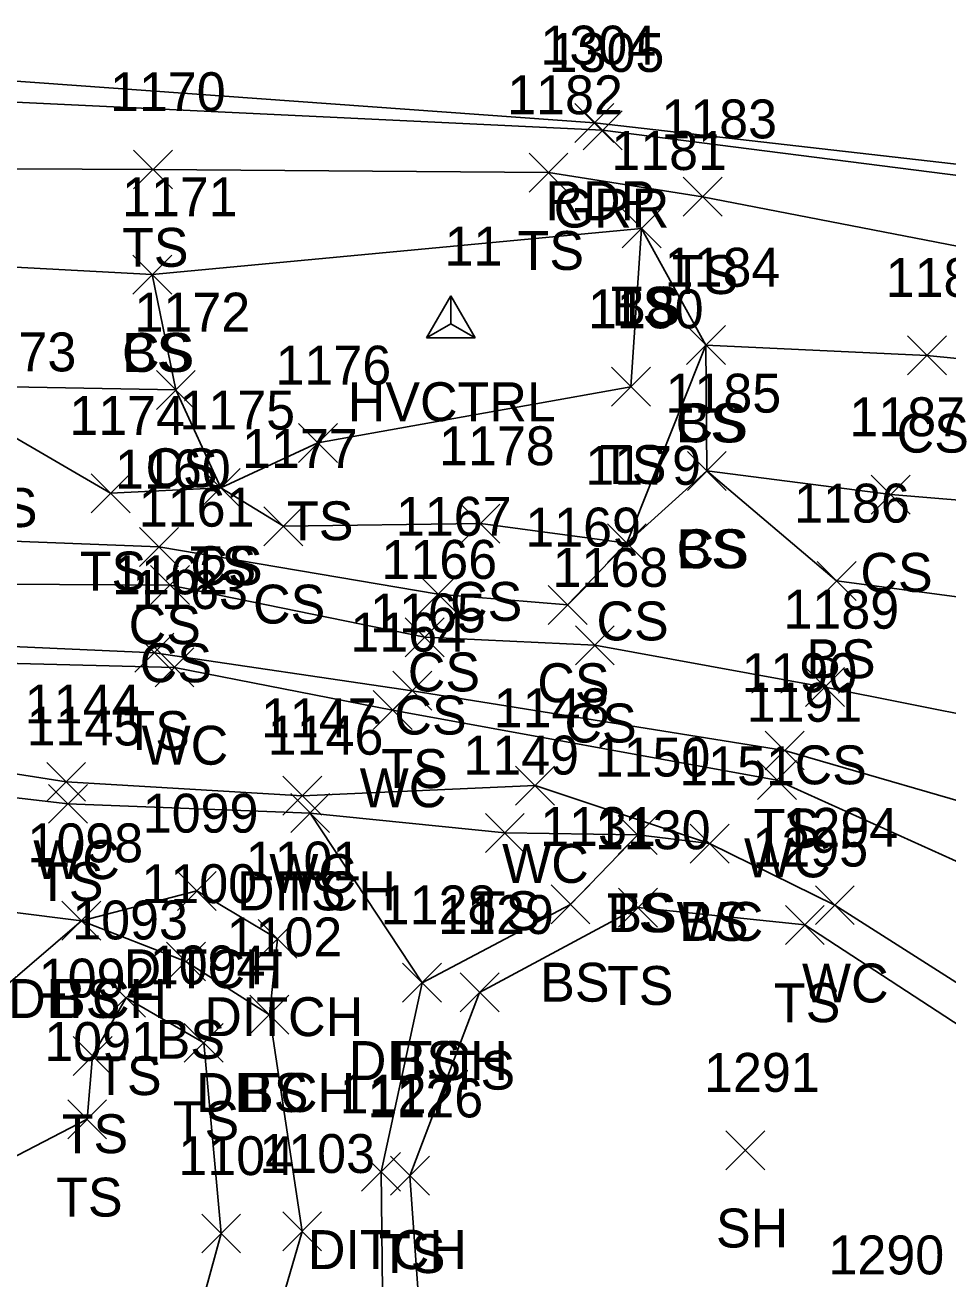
# Model space of a CAD drawing. Extents: x 1514253 to 1516033, y 782541 to 785002.
# Drawn here: x 1515320.5 to 1515367.9, y 782620.4 to 782684.8 of the extents above; entities that cross this region are included whole.
import ezdxf

# ---------------------------------------------------------------- set-up
doc = ezdxf.new("R2010")
doc.units = 0
for name, color, linetype in [('C_A', 7, 'Continuous'), ('C_I', 7, 'Continuous'), ('CPSM', 7, 'Continuous'), ('D_A', 7, 'Continuous'), ('D_I', 7, 'Continuous'), ('D_TIC', 7, 'Continuous'), ('DD', 7, 'Continuous'), ('L_A', 7, 'Continuous'), ('L_I', 7, 'Continuous'), ('L_TIC', 7, 'Continuous'), ('LAWE', 7, 'Continuous'), ('LELB', 7, 'Continuous'), ('P_A', 7, 'Continuous'), ('P_I', 7, 'Continuous'), ('P_TIC', 7, 'Continuous'), ('PET', 7, 'Continuous'), ('R_A', 7, 'Continuous'), ('R_I', 7, 'Continuous'), ('R_TIC', 7, 'Continuous'), ('RGR', 7, 'Continuous')]:
    doc.layers.add(name, color=color, linetype=linetype)

msp = doc.modelspace()

# ---------------------------------------------------------------- linework, layer by layer
at = {"layer": 'CPSM'}
for p, q in [((1515341.122, 782668.734), (1515342.372, 782670.899)), ((1515343.622, 782668.734), (1515342.372, 782670.899)), ((1515342.372, 782669.456), (1515342.372, 782670.899)), ((1515341.122, 782668.734), (1515342.372, 782669.456)), ((1515342.372, 782669.456), (1515342.372, 782669.456)), ((1515342.372, 782669.456), (1515343.622, 782668.734)), ((1515341.122, 782668.734), (1515343.622, 782668.734))]:
    msp.add_line(p, q, dxfattribs=at)
at = {"layer": 'D_TIC'}
for points in [[(1515334.13, 782643.312), (1515336.13, 782645.312)], [(1515336.13, 782643.312), (1515334.13, 782645.312)], [(1515328.306, 782639.309), (1515330.306, 782641.309)], [(1515330.306, 782639.309), (1515328.306, 782641.309)], [(1515322.367, 782637.781), (1515324.367, 782639.781)], [(1515324.367, 782637.781), (1515322.367, 782639.781)], [(1515332.451, 782636.848), (1515334.451, 782638.848)], [(1515334.451, 782636.848), (1515332.451, 782638.848)], [(1515339.884, 782634.592), (1515341.884, 782636.592)], [(1515341.884, 782634.592), (1515339.884, 782636.592)], [(1515332.036, 782632.949), (1515334.036, 782634.949)], [(1515334.036, 782632.949), (1515332.036, 782634.949)], [(1515337.78, 782624.875), (1515339.78, 782626.875)], [(1515339.78, 782624.875), (1515337.78, 782626.875)], [(1515333.721, 782621.814), (1515335.721, 782623.814)], [(1515335.721, 782621.814), (1515333.721, 782623.814)]]:
    msp.add_lwpolyline(points, dxfattribs=at)
at = {"layer": 'DD'}
for points in [[(1515199.394, 782648.84), (1515235.483, 782648.45), (1515272.163, 782648.844), (1515285.608, 782648.488), (1515294.464, 782648.384), (1515312.17, 782640.182), (1515323.367, 782638.781), (1515329.306, 782640.309), (1515333.451, 782637.848), (1515333.036, 782633.949), (1515334.721, 782622.814), (1515328.394, 782601.12)], [(1515357.883, 782606.277), (1515350.175, 782606.05), (1515345.522, 782607.313), (1515338.903, 782615.134), (1515338.78, 782625.875), (1515340.884, 782635.592), (1515335.13, 782644.312)]]:
    msp.add_lwpolyline(points, dxfattribs=at)
at = {"layer": 'L_TIC'}
for points in [[(1515326.05, 782676.392), (1515328.05, 782678.392)], [(1515328.05, 782676.392), (1515326.05, 782678.392)], [(1515346.388, 782676.23), (1515348.388, 782678.23)], [(1515348.388, 782676.23), (1515346.388, 782678.23)], [(1515354.314, 782674.991), (1515356.314, 782676.991)], [(1515356.314, 782674.991), (1515354.314, 782676.991)], [(1515351.175, 782673.367), (1515353.175, 782675.367)], [(1515353.175, 782673.367), (1515351.175, 782675.367)], [(1515351.175, 782673.367), (1515353.175, 782675.367)], [(1515353.175, 782673.367), (1515351.175, 782675.367)], [(1515326.016, 782670.989), (1515328.016, 782672.989)], [(1515328.016, 782670.989), (1515326.016, 782672.989)], [(1515326.016, 782670.989), (1515328.016, 782672.989)], [(1515328.016, 782670.989), (1515326.016, 782672.989)], [(1515354.484, 782667.368), (1515356.484, 782669.368)], [(1515356.484, 782667.368), (1515354.484, 782669.368)], [(1515354.484, 782667.368), (1515356.484, 782669.368)], [(1515356.484, 782667.368), (1515354.484, 782669.368)], [(1515365.848, 782666.84), (1515367.848, 782668.84)], [(1515367.848, 782666.84), (1515365.848, 782668.84)], [(1515327.224, 782665.061), (1515329.224, 782667.061)], [(1515329.224, 782665.061), (1515327.224, 782667.061)], [(1515327.224, 782665.061), (1515329.224, 782667.061)], [(1515329.224, 782665.061), (1515327.224, 782667.061)], [(1515350.626, 782665.228), (1515352.626, 782667.228)], [(1515352.626, 782665.228), (1515350.626, 782667.228)], [(1515334.531, 782662.335), (1515336.531, 782664.335)], [(1515336.531, 782662.335), (1515334.531, 782664.335)], [(1515354.529, 782660.896), (1515356.529, 782662.896)], [(1515356.529, 782660.896), (1515354.529, 782662.896)], [(1515354.529, 782660.896), (1515356.529, 782662.896)], [(1515356.529, 782660.896), (1515354.529, 782662.896)], [(1515329.533, 782660.03), (1515331.533, 782662.03)], [(1515331.533, 782660.03), (1515329.533, 782662.03)], [(1515329.533, 782660.03), (1515331.533, 782662.03)], [(1515331.533, 782660.03), (1515329.533, 782662.03)], [(1515323.873, 782659.753), (1515325.873, 782661.753)], [(1515325.873, 782659.753), (1515323.873, 782661.753)], [(1515363.984, 782659.684), (1515365.984, 782661.684)], [(1515365.984, 782659.684), (1515363.984, 782661.684)], [(1515332.755, 782658.052), (1515334.755, 782660.052)], [(1515334.755, 782658.052), (1515332.755, 782660.052)], [(1515342.884, 782658.192), (1515344.884, 782660.192)], [(1515344.884, 782658.192), (1515342.884, 782660.192)], [(1515326.358, 782656.995), (1515328.358, 782658.995)], [(1515328.358, 782656.995), (1515326.358, 782658.995)], [(1515350.413, 782657.187), (1515352.413, 782659.187)], [(1515352.413, 782657.187), (1515350.413, 782659.187)], [(1515350.413, 782657.187), (1515352.413, 782659.187)], [(1515352.413, 782657.187), (1515350.413, 782659.187)], [(1515326.927, 782655.035), (1515328.927, 782657.035)], [(1515328.927, 782655.035), (1515326.927, 782657.035)], [(1515361.199, 782655.243), (1515363.199, 782657.243)], [(1515363.199, 782655.243), (1515361.199, 782657.243)], [(1515340.712, 782654.566), (1515342.712, 782656.566)], [(1515342.712, 782654.566), (1515340.712, 782656.566)], [(1515347.371, 782654.012), (1515349.371, 782656.012)], [(1515349.371, 782654.012), (1515347.371, 782656.012)], [(1515340.024, 782652.35), (1515342.024, 782654.35)], [(1515342.024, 782652.35), (1515340.024, 782654.35)], [(1515326.12, 782651.556), (1515328.12, 782653.556)], [(1515328.12, 782651.556), (1515326.12, 782653.556)], [(1515348.767, 782651.941), (1515350.767, 782653.941)], [(1515350.767, 782651.941), (1515348.767, 782653.941)], [(1515327.158, 782650.8), (1515329.158, 782652.8)], [(1515329.158, 782650.8), (1515327.158, 782652.8)], [(1515339.38, 782649.599), (1515341.38, 782651.599)], [(1515341.38, 782649.599), (1515339.38, 782651.599)], [(1515360.602, 782649.791), (1515362.602, 782651.791)], [(1515362.602, 782649.791), (1515360.602, 782651.791)], [(1515338.372, 782648.611), (1515340.372, 782650.611)], [(1515340.372, 782648.611), (1515338.372, 782650.611)], [(1515358.526, 782646.53), (1515360.526, 782648.53)], [(1515360.526, 782646.53), (1515358.526, 782648.53)], [(1515321.585, 782644.92), (1515323.585, 782646.92)], [(1515323.585, 782644.92), (1515321.585, 782646.92)], [(1515345.696, 782644.723), (1515347.696, 782646.723)], [(1515347.696, 782644.723), (1515345.696, 782646.723)], [(1515358.133, 782645.008), (1515360.133, 782647.008)], [(1515360.133, 782645.008), (1515358.133, 782647.008)], [(1515321.678, 782643.788), (1515323.678, 782645.788)], [(1515323.678, 782643.788), (1515321.678, 782645.788)], [(1515333.724, 782644.203), (1515335.724, 782646.203)], [(1515335.724, 782644.203), (1515333.724, 782646.203)], [(1515334.13, 782643.312), (1515336.13, 782645.312)], [(1515336.13, 782643.312), (1515334.13, 782645.312)], [(1515344.143, 782642.295), (1515346.143, 782644.295)], [(1515346.143, 782642.295), (1515344.143, 782644.295)], [(1515350.972, 782642.192), (1515352.972, 782644.192)], [(1515352.972, 782642.192), (1515350.972, 782644.192)], [(1515350.972, 782642.192), (1515352.972, 782644.192)], [(1515352.972, 782642.192), (1515350.972, 782644.192)], [(1515354.669, 782641.743), (1515356.669, 782643.743)], [(1515356.669, 782641.743), (1515354.669, 782643.743)], [(1515354.669, 782641.743), (1515356.669, 782643.743)], [(1515356.669, 782641.743), (1515354.669, 782643.743)], [(1515347.518, 782638.619), (1515349.518, 782640.619)], [(1515349.518, 782638.619), (1515347.518, 782640.619)], [(1515350.986, 782638.451), (1515352.986, 782640.451)], [(1515352.986, 782638.451), (1515350.986, 782640.451)], [(1515361.112, 782638.578), (1515363.112, 782640.578)], [(1515363.112, 782638.578), (1515361.112, 782640.578)], [(1515361.112, 782638.578), (1515363.112, 782640.578)], [(1515363.112, 782638.578), (1515361.112, 782640.578)], [(1515322.367, 782637.781), (1515324.367, 782639.781)], [(1515324.367, 782637.781), (1515322.367, 782639.781)], [(1515359.567, 782637.564), (1515361.567, 782639.564)], [(1515361.567, 782637.564), (1515359.567, 782639.564)], [(1515359.567, 782637.564), (1515361.567, 782639.564)], [(1515361.567, 782637.564), (1515359.567, 782639.564)], [(1515327.746, 782635.685), (1515329.746, 782637.685)], [(1515329.746, 782635.685), (1515327.746, 782637.685)], [(1515339.884, 782634.592), (1515341.884, 782636.592)], [(1515341.884, 782634.592), (1515339.884, 782636.592)], [(1515342.846, 782634.098), (1515344.846, 782636.098)], [(1515344.846, 782634.098), (1515342.846, 782636.098)], [(1515324.669, 782633.817), (1515326.669, 782635.817)], [(1515326.669, 782633.817), (1515324.669, 782635.817)], [(1515332.036, 782632.949), (1515334.036, 782634.949)], [(1515334.036, 782632.949), (1515332.036, 782634.949)], [(1515328.658, 782631.505), (1515330.658, 782633.505)], [(1515330.658, 782631.505), (1515328.658, 782633.505)], [(1515322.948, 782630.832), (1515324.948, 782632.832)], [(1515324.948, 782630.832), (1515322.948, 782632.832)], [(1515322.664, 782627.572), (1515324.664, 782629.572)], [(1515324.664, 782627.572), (1515322.664, 782629.572)], [(1515356.511, 782625.984), (1515358.511, 782627.984)], [(1515358.511, 782625.984), (1515356.511, 782627.984)], [(1515339.261, 782624.67), (1515341.261, 782626.67)], [(1515341.261, 782624.67), (1515339.261, 782626.67)], [(1515329.558, 782621.703), (1515331.558, 782623.703)], [(1515331.558, 782621.703), (1515329.558, 782623.703)]]:
    msp.add_lwpolyline(points, dxfattribs=at)
at = {"layer": 'LAWE'}
for points in [[(1515305.221, 782658.389), (1515303.181, 782657.217), (1515302.59, 782655.701), (1515303.77, 782652.127), (1515308.32, 782648.165), (1515322.585, 782645.92), (1515334.724, 782645.203), (1515346.696, 782645.723), (1515355.669, 782642.743), (1515362.112, 782639.578)], [(1515305.221, 782658.389), (1515309.247, 782657.829), (1515309.37, 782656.024), (1515310.661, 782652.237), (1515328.158, 782651.8), (1515339.372, 782649.611), (1515359.133, 782646.008), (1515370.291, 782640.974), (1515378.24, 782634.81), (1515385.256, 782635.895), (1515388.599, 782640.179), (1515389.121, 782646.36), (1515386.777, 782649.906), (1515390.568, 782651.945), (1515397.927, 782652.705), (1515407.459, 782649.219), (1515414.933, 782648.068), (1515419.945, 782646.777), (1515424.071, 782644.52), (1515427.947, 782638.847), (1515430.432, 782625.437), (1515426.178, 782619.034), (1515431.378, 782612.516)], [(1515425.881, 782608.624), (1515417.686, 782620.679), (1515422.974, 782628.809), (1515420.872, 782635.955), (1515417.164, 782641.13), (1515411.117, 782642.694), (1515398.91, 782647.419), (1515394.909, 782646.476), (1515394.422, 782644.041), (1515394.489, 782636.861), (1515393.182, 782628.813), (1515387.524, 782628.807), (1515379.253, 782626.313), (1515373.238, 782632.504), (1515362.112, 782639.578)]]:
    msp.add_lwpolyline(points, dxfattribs=at)
at = {"layer": 'LELB'}
for points in [[(1515198.723, 782678.684), (1515237.654, 782681.037), (1515272.581, 782680.406), (1515290.322, 782679.158), (1515303.85, 782678.499), (1515308.9, 782677.477), (1515327.05, 782677.392), (1515347.388, 782677.23), (1515355.314, 782675.991), (1515384.856, 782670.273), (1515402.641, 782668.137), (1515426.898, 782664.758), (1515431.084, 782662.879), (1515448.442, 782660.296)], [(1515199.146, 782675.609), (1515237.424, 782674.791), (1515272.569, 782675.732), (1515289.461, 782673.873), (1515300.027, 782673.178), (1515309.403, 782672.939), (1515327.016, 782671.989), (1515352.175, 782674.367), (1515355.484, 782668.368), (1515355.529, 782661.896), (1515362.199, 782656.243), (1515384.653, 782653.272), (1515398.956, 782656.377), (1515406.884, 782653.846), (1515416.301, 782653.121), (1515424.335, 782655.884), (1515430.378, 782659.607), (1515449.299, 782656.525)], [(1515199.979, 782655.093), (1515236.324, 782655.449), (1515273.423, 782656.598), (1515286.933, 782662.615), (1515299.54, 782665.004), (1515304.675, 782664.101), (1515305.267, 782661.39), (1515319.285, 782664.015), (1515324.873, 782660.753), (1515330.533, 782661.03), (1515335.531, 782663.335), (1515351.626, 782666.228), (1515352.175, 782674.367)], [(1515199.887, 782668.087), (1515237.312, 782668.583), (1515273.401, 782672.059), (1515287.729, 782668.029), (1515299.264, 782668.757), (1515308.354, 782666.42), (1515328.224, 782666.061), (1515330.533, 782661.03), (1515333.755, 782659.052), (1515343.884, 782659.192), (1515351.413, 782658.187), (1515355.484, 782668.368), (1515366.848, 782667.84), (1515384.002, 782666.142), (1515400.676, 782664.245), (1515424.648, 782661.721), (1515431.013, 782661.432), (1515448.86, 782658.438)], [(1515327.016, 782671.989), (1515328.224, 782666.061)], [(1515284.508, 782654.562), (1515294.334, 782657.273), (1515301.485, 782657.951), (1515303.943, 782660.043), (1515308.932, 782660.064), (1515315.851, 782658.437), (1515327.358, 782657.995), (1515341.712, 782655.566), (1515348.371, 782655.012), (1515351.413, 782658.187), (1515355.529, 782661.896), (1515364.984, 782660.684), (1515382.517, 782659.229), (1515399.983, 782660.3), (1515424.268, 782658.95)], [(1515309.247, 782657.829), (1515310.163, 782657.372), (1515313.696, 782656.121), (1515327.927, 782656.035), (1515341.024, 782653.35), (1515349.767, 782652.941), (1515361.602, 782650.791), (1515374.165, 782648.283), (1515380.971, 782647.67), (1515386.077, 782649.544)], [(1515310.163, 782657.372), (1515310.383, 782655.934), (1515311.738, 782653.239), (1515327.12, 782652.556), (1515340.38, 782650.599), (1515359.526, 782647.53), (1515371.713, 782643.995), (1515378.608, 782636.912), (1515384.051, 782637.622), (1515387.007, 782640.366), (1515387.011, 782646.011), (1515386.077, 782649.544), (1515388.534, 782653.757), (1515398.392, 782653.907), (1515407.552, 782650.359), (1515415.675, 782649.762), (1515419.247, 782648.751), (1515425.267, 782646.15), (1515433.214, 782625.745), (1515427.667, 782618.999), (1515432.728, 782613.436)], [(1515301.839, 782655.709), (1515302.751, 782650.961), (1515307.982, 782646.496), (1515322.678, 782644.788), (1515335.13, 782644.312), (1515345.143, 782643.295), (1515351.972, 782643.192)], [(1515267.096, 782619.076), (1515273.864, 782624.863), (1515276.319, 782635.308), (1515279.925, 782643.508), (1515284.876, 782645.286), (1515293.699, 782642.978), (1515298.257, 782639.773), (1515306.339, 782638.14), (1515312.767, 782632.766), (1515316.681, 782633.039), (1515323.367, 782638.781), (1515328.746, 782636.685), (1515333.036, 782633.949)], [(1515424.462, 782608.5), (1515416.13, 782621.2), (1515420.279, 782628.005), (1515420.055, 782635.411), (1515415.778, 782639.443), (1515407.458, 782642.731), (1515398.549, 782645.643), (1515395.171, 782636.9), (1515393.589, 782628.83), (1515388.008, 782625.21), (1515377.827, 782623.514), (1515372.602, 782630.72), (1515360.567, 782638.564)], [(1515340.884, 782635.592), (1515348.518, 782639.619), (1515351.972, 782643.192), (1515355.669, 782642.743)], [(1515267.493, 782617.708), (1515275.905, 782623.682), (1515279.076, 782634.626), (1515280.627, 782640.948), (1515290.641, 782638.315), (1515296.789, 782634.635), (1515304.473, 782631.621), (1515309.893, 782622.536), (1515316.95, 782625.103), (1515323.664, 782628.572), (1515323.948, 782631.832), (1515325.669, 782634.817), (1515329.658, 782632.505), (1515330.558, 782622.703), (1515325.128, 782602.902)], [(1515357.883, 782606.277), (1515350.282, 782607.324), (1515345.922, 782608.145), (1515341.013, 782615.1), (1515340.261, 782625.67), (1515343.846, 782635.098), (1515351.986, 782639.451), (1515360.567, 782638.564)]]:
    msp.add_lwpolyline(points, dxfattribs=at)
at = {"layer": 'P_TIC'}
for points in [[(1515348.744, 782678.786), (1515350.744, 782680.786)], [(1515350.744, 782678.786), (1515348.744, 782680.786)]]:
    msp.add_lwpolyline(points, dxfattribs=at)
at = {"layer": 'PET'}
msp.add_lwpolyline([(1515199.633, 782684.061), (1515237.525, 782684.632), (1515272.463, 782684.04), (1515305.734, 782682.962), (1515349.744, 782679.786), (1515389.071, 782675.303), (1515418.681, 782671.113), (1515450.732, 782666.149)], dxfattribs=at)
at = {"layer": 'R_TIC'}
for points in [[(1515349.167, 782678.409), (1515351.167, 782680.409)], [(1515351.167, 782678.409), (1515349.167, 782680.409)]]:
    msp.add_lwpolyline(points, dxfattribs=at)
at = {"layer": 'RGR'}
msp.add_lwpolyline([(1515199.059, 782680.993), (1515237.496, 782683.643), (1515272.426, 782683.075), (1515305.957, 782681.521), (1515350.167, 782679.409), (1515389.004, 782674.461), (1515418.688, 782670.319), (1515449.265, 782662.37)], dxfattribs=at)

# ---------------------------------------------------------------- texts
at = {"layer": 'C_A'}
msp.add_text('HVCTRL', height=2, dxfattribs=at).set_placement((1515337.065, 782664.456))
at = {"layer": 'C_I'}
msp.add_text('11', height=2, dxfattribs=at).set_placement((1515342.041, 782672.456))
at = {"layer": 'D_A'}
for p in [(1515331.366, 782639.312), (1515325.542, 782635.309), (1515319.603, 782633.781), (1515329.687, 782632.848), (1515337.121, 782630.592), (1515329.272, 782628.949), (1515335.016, 782620.875)]:
    msp.add_text('DITCH', height=2, dxfattribs=at).set_placement(p)
at = {"layer": 'D_I'}
for s, p in [('1146', (1515332.949, 782647.312)), ('1099', (1515326.526, 782643.309)), ('1098', (1515320.596, 782641.781)), ('1101', (1515331.813, 782640.848)), ('1128', (1515338.758, 782638.592)), ('1102', (1515330.831, 782636.949)), ('1127', (1515336.654, 782628.875)), ('1103', (1515332.516, 782625.814))]:
    msp.add_text(s, height=2, dxfattribs=at).set_placement(p)
at = {"layer": 'L_A'}
for s, p in [('TS', (1515325.46, 782672.392)), ('TS', (1515345.797, 782672.23)), ('TS', (1515353.723, 782670.991)), ('TS', (1515350.585, 782669.367)), ('BS', (1515350.616, 782669.367)), ('CS', (1515325.457, 782666.989)), ('BS', (1515325.457, 782666.989)), ('CS', (1515353.925, 782663.368)), ('BS', (1515353.925, 782663.368)), ('CS', (1515365.289, 782662.84)), ('TS', (1515350.035, 782661.228)), ('CS', (1515326.665, 782661.061)), ('CS', (1515326.665, 782661.061)), ('TS', (1515317.694, 782659.015)), ('TS', (1515333.941, 782658.335)), ('CS', (1515353.97, 782656.896)), ('BS', (1515353.97, 782656.896)), ('TS', (1515328.943, 782656.03)), ('CS', (1515328.974, 782656.03)), ('TS', (1515323.282, 782655.753)), ('CS', (1515363.425, 782655.684)), ('CS', (1515332.196, 782654.052)), ('CS', (1515342.325, 782654.192)), ('CS', (1515325.799, 782652.995)), ('CS', (1515349.853, 782653.187)), ('CS', (1515349.853, 782653.187)), ('CS', (1515326.368, 782651.035)), ('BS', (1515360.64, 782651.243)), ('CS', (1515340.153, 782650.566)), ('CS', (1515346.812, 782650.012)), ('CS', (1515339.465, 782648.35)), ('CS', (1515348.208, 782647.941)), ('TS', (1515325.53, 782647.556)), ('WC', (1515326.465, 782646.8)), ('CS', (1515360.043, 782645.791)), ('TS', (1515338.79, 782645.599)), ('WC', (1515337.679, 782644.611)), ('TS', (1515357.935, 782642.53)), ('WC', (1515320.892, 782640.92)), ('WC', (1515345.003, 782640.723)), ('WC', (1515357.44, 782641.008)), ('WC', (1515333.031, 782640.203)), ('TS', (1515321.088, 782639.788)), ('TS', (1515333.54, 782639.312)), ('TS', (1515343.552, 782638.295)), ('TS', (1515350.381, 782638.192)), ('BS', (1515350.413, 782638.192)), ('WC', (1515353.976, 782637.743)), ('BS', (1515354.109, 782637.743)), ('BS', (1515346.959, 782634.619)), ('TS', (1515350.396, 782634.451)), ('WC', (1515360.419, 782634.578)), ('WC', (1515360.419, 782634.578)), ('BS', (1515321.808, 782633.781)), ('TS', (1515358.977, 782633.564)), ('TS', (1515358.977, 782633.564)), ('BS', (1515327.187, 782631.685)), ('BS', (1515339.325, 782630.592)), ('TS', (1515324.078, 782629.817)), ('TS', (1515342.255, 782630.098)), ('BS', (1515331.477, 782628.949)), ('TS', (1515328.068, 782627.505)), ('TS', (1515322.357, 782626.832)), ('TS', (1515322.073, 782623.572)), ('SH', (1515355.999, 782621.984)), ('TS', (1515338.67, 782620.67))]:
    msp.add_text(s, height=2, dxfattribs=at).set_placement(p)
at = {"layer": 'L_I'}
for s, p in [('1170', (1515324.838, 782680.392)), ('1182', (1515345.262, 782680.23)), ('1183', (1515353.188, 782678.991)), ('1181', (1515350.616, 782677.367)), ('1181', (1515350.616, 782677.367)), ('1171', (1515325.457, 782674.989)), ('1171', (1515325.457, 782674.989)), ('1184', (1515353.358, 782671.368)), ('1184', (1515353.358, 782671.368)), ('1188', (1515364.722, 782670.84)), ('1172', (1515326.098, 782669.061)), ('1172', (1515326.098, 782669.061)), ('1180', (1515349.413, 782669.228)), ('1173', (1515317.159, 782667.015)), ('1176', (1515333.35, 782666.335)), ('1185', (1515353.403, 782664.896)), ('1185', (1515353.403, 782664.896)), ('1174', (1515322.747, 782663.753)), ('1175', (1515328.407, 782664.03)), ('1175', (1515328.407, 782664.03)), ('1187', (1515362.858, 782663.684)), ('1177', (1515331.629, 782662.052)), ('1178', (1515341.758, 782662.192)), ('1179', (1515349.279, 782661.187)), ('1179', (1515349.279, 782661.187)), ('1160', (1515325.098, 782660.995)), ('1186', (1515360.018, 782659.243)), ('1161', (1515326.321, 782659.035)), ('1167', (1515339.539, 782658.566)), ('1169', (1515346.19, 782658.012)), ('1166', (1515338.796, 782656.35)), ('1162', (1515324.947, 782655.556)), ('1168', (1515347.594, 782655.941)), ('1163', (1515325.984, 782654.8)), ('1165', (1515338.207, 782653.599)), ('1189', (1515359.468, 782653.791)), ('1164', (1515337.199, 782652.611)), ('1190', (1515357.313, 782650.53)), ('1144', (1515320.459, 782648.92)), ('1191', (1515357.574, 782649.008)), ('1148', (1515344.57, 782648.723)), ('1145', (1515320.552, 782647.788)), ('1147', (1515332.598, 782648.203)), ('1146', (1515332.949, 782647.312)), ('1149', (1515343.009, 782646.295)), ('1150', (1515349.759, 782646.192)), ('1150', (1515349.759, 782646.192)), ('1151', (1515354.109, 782645.743)), ('1151', (1515354.109, 782645.743)), ('1131', (1515346.959, 782642.619)), ('1130', (1515349.774, 782642.451)), ('1294', (1515359.419, 782642.578)), ('1294', (1515359.419, 782642.578)), ('1098', (1515320.596, 782641.781)), ('1295', (1515357.874, 782641.564)), ('1295', (1515357.874, 782641.564)), ('1100', (1515326.455, 782639.685)), ('1128', (1515338.758, 782638.592)), ('1129', (1515341.712, 782638.098)), ('1093', (1515322.897, 782637.817)), ('1102', (1515330.831, 782636.949)), ('1094', (1515326.886, 782635.505)), ('1092', (1515321.176, 782634.832)), ('1091', (1515321.459, 782631.572)), ('1291', (1515355.385, 782629.984)), ('1126', (1515338.08, 782628.67)), ('1104', (1515328.354, 782625.703)), ('1290', (1515361.784, 782620.601))]:
    msp.add_text(s, height=2, dxfattribs=at).set_placement(p)
at = {"layer": 'P_A'}
msp.add_text('RDP', height=2, dxfattribs=at).set_placement((1515347.232, 782674.786))
at = {"layer": 'P_I'}
msp.add_text('1304', height=2, dxfattribs=at).set_placement((1515346.972, 782682.786))
at = {"layer": 'R_A'}
msp.add_text('GRR', height=2, dxfattribs=at).set_placement((1515347.655, 782674.409))
at = {"layer": 'R_I'}
msp.add_text('1305', height=2, dxfattribs=at).set_placement((1515347.395, 782682.409))

doc.saveas('drawing.dxf')
